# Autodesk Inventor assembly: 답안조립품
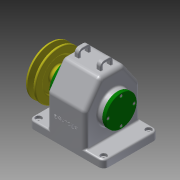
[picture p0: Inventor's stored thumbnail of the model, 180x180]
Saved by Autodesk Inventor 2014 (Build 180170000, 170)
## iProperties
Created: 2016-12
Part Number: 답안조립품
Document SubType Name: Assembly
Designer: USER
Author: USER
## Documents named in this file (15)
- C:\Users\USER\Desktop\461208V1020\답안조립품.iam
- C:\Users\USER\Desktop\461208V1020\본체.ipt
- C:\Users\USER\Desktop\461208V1020\뒤커버.ipt
- C:\Users\USER\Desktop\461208V1020\볼트 M3 x 8.ipt
- C:\Users\USER\Desktop\461208V1020\베어링 6203.ipt
- C:\Users\USER\Desktop\461208V1020\축.ipt
- C:\Users\USER\Desktop\461208V1020\키 - 6 x 6 x 22.ipt
- C:\Users\USER\Desktop\461208V1020\스퍼기어.ipt
- C:\Users\USER\Desktop\461208V1020\부시.ipt
- C:\Users\USER\Desktop\461208V1020\앞커버.ipt
- C:\Users\USER\Desktop\461208V1020\볼트 M3 x 10.ipt
- C:\Users\USER\Desktop\461208V1020\키 - 5 x 5 x 18.ipt
- C:\Users\USER\Desktop\461208V1020\V-벨트풀리.ipt
- C:\Users\USER\Desktop\461208V1020\멈춤나사 - M4x10.ipt
- C:\Users\USER\Desktop\461208V1020\오일씰 28 40 8.ipt
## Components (9 placed, 3 different names)
1. V-벨트풀리:1
2. ISO 4762 M3 x 8:1
3. ISO 4762 M3 x 8:2
4. ISO 4762 M3 x 8:3
5. ISO 4762 M3 x 8:4
6. ISO 4762 M3 x 10:1
7. ISO 4762 M3 x 10:2
8. ISO 4762 M3 x 10:3
9. ISO 4762 M3 x 10:4
